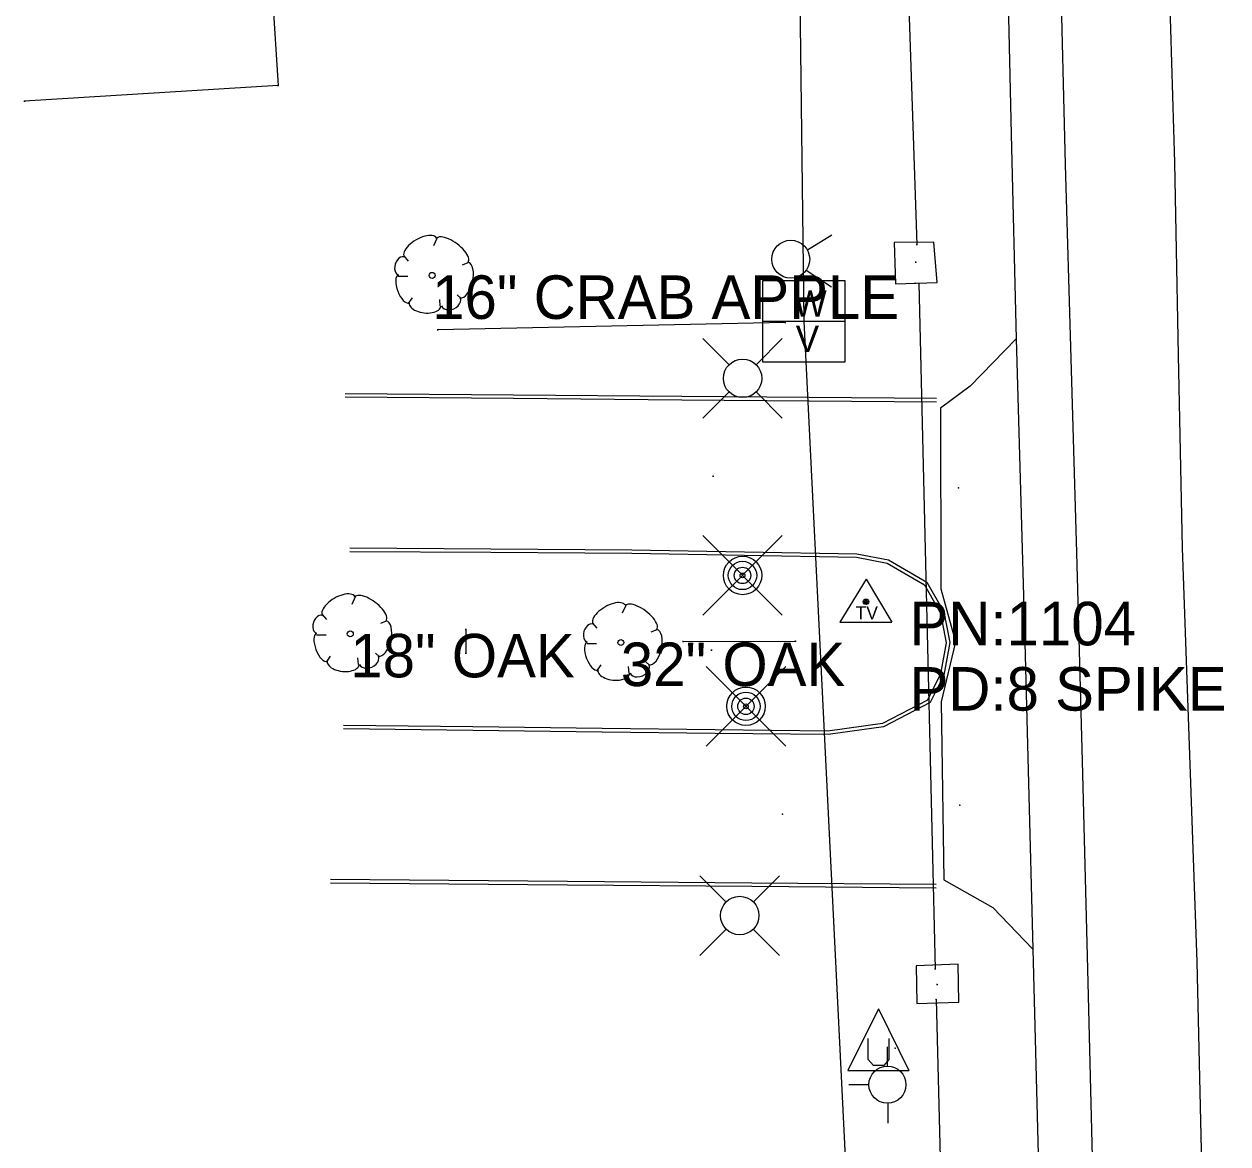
# Model space of a CAD drawing. Extents: x 1930288 to 1941089, y 588389 to 611475.
# Drawn here: x 1930751.7 to 1930890, y 597675.1 to 597803.8 of the extents above; entities that cross this region are included whole.
import ezdxf

# ---------------------------------------------------------------- set-up
doc = ezdxf.new("R2010")
doc.units = 0
for name, color, linetype in [('S_BUILDING', 7, 'Continuous'), ('S_CURB', 7, 'Continuous'), ('S_DRG_PT_SYM', 7, 'Continuous'), ('S_DRIVEWAY', 7, 'Continuous'), ('S_DROP_INLET', 7, 'Continuous'), ('S_EDGE_PAVEMENT', 7, 'Continuous'), ('S_LANDSCAPING', 7, 'Continuous'), ('S_MSC_PT_SYM', 7, 'Continuous'), ('S_PAVEMENT_CROWN', 7, 'Continuous'), ('S_SECONDARY_CTL', 7, 'Continuous'), ('S_SECONDARY_CTL_ANNOT', 7, 'Continuous'), ('S_SHOULDER', 7, 'Continuous'), ('S_SIGN', 7, 'Continuous'), ('S_STORM_SEWER', 7, 'Continuous'), ('S_STR_PT_SYM', 7, 'Continuous'), ('S_TREE', 7, 'Continuous'), ('S_TREE_ANNOT', 7, 'Continuous'), ('S_UNDERGROUND_CABLE', 7, 'Continuous'), ('S_UTILITY_POLE', 7, 'Continuous'), ('S_UTL_PT_SYM', 7, 'Continuous'), ('S_WATER_UTILITIES', 7, 'Continuous')]:
    doc.layers.add(name, color=color, linetype=linetype)

msp = doc.modelspace()

# ---------------------------------------------------------------- linework, layer by layer
at = {"layer": 'S_BUILDING'}
for p, q in [((1930779.32, 597821.17), (1930780.88, 597796.72)), ((1930780.88, 597796.72), (1930751.75, 597794.9))]:
    msp.add_line(p, q, dxfattribs=at)
at = {"layer": 'S_CURB'}
for points in [[(1930856.53, 597760.35), (1930841.9, 597760.46), (1930827.27, 597760.58), (1930807.94, 597760.74), (1930788.6, 597760.9)], [(1930856.53, 597760.75), (1930841.9, 597760.86), (1930827.27, 597760.98), (1930807.94, 597761.14), (1930788.61, 597761.3)], [(1930789.14, 597743.59), (1930805.34, 597743.49), (1930821.54, 597743.39), (1930834.46, 597743.16), (1930847.39, 597742.92), (1930851, 597742.23), (1930855.42, 597739.66), (1930857.37, 597736.24), (1930858.06, 597732.71), (1930857.37, 597728.98), (1930855.78, 597725.82), (1930850.43, 597723.02), (1930844.08, 597722.15), (1930831.1, 597722.29), (1930818.13, 597722.44), (1930803.26, 597722.62), (1930788.39, 597722.8)], [(1930789.14, 597743.19), (1930805.33, 597743.09), (1930821.53, 597742.99), (1930834.44, 597742.76), (1930847.35, 597742.52), (1930850.86, 597741.85), (1930855.13, 597739.36), (1930856.99, 597736.1), (1930857.65, 597732.7), (1930856.99, 597729.11), (1930855.48, 597726.12), (1930850.31, 597723.41), (1930844.06, 597722.55), (1930831.09, 597722.69), (1930818.13, 597722.84), (1930803.27, 597723.02), (1930788.4, 597723.2)], [(1930786.9, 597705.53), (1930800.51, 597705.41), (1930814.12, 597705.3), (1930835.31, 597705.13), (1930856.49, 597704.96)], [(1930786.9, 597705.13), (1930800.51, 597705.01), (1930814.12, 597704.9), (1930835.3, 597704.73), (1930856.49, 597704.56)]]:
    msp.add_lwpolyline(points, dxfattribs=at)
at = {"layer": 'S_DRG_PT_SYM'}
for points in [[(1930854.14, 597776.42), (1930854.14, 597776.47), (1930854.14, 597776.42), (1930854.09, 597776.42), (1930854.14, 597776.42), (1930854.14, 597776.37), (1930854.14, 597776.42), (1930854.19, 597776.42)], [(1930856.59, 597693.44), (1930856.59, 597693.49), (1930856.59, 597693.44), (1930856.54, 597693.44), (1930856.59, 597693.44), (1930856.59, 597693.39), (1930856.59, 597693.44), (1930856.64, 597693.44)]]:
    msp.add_lwpolyline(points, dxfattribs=at)
at = {"layer": 'S_DRIVEWAY'}
msp.add_lwpolyline([(1930865.66, 597767.61), (1930860.41, 597762.17), (1930856.98, 597759.65), (1930857.04, 597738.91), (1930858.7, 597732.8), (1930857.08, 597725.9), (1930857.36, 597705.47), (1930863.01, 597702.28), (1930867.6, 597697.51)], dxfattribs=at)
at = {"layer": 'S_DROP_INLET'}
for points in [[(1930851.66, 597778.68), (1930851.81, 597773.94), (1930856.61, 597774.1), (1930856.23, 597778.7)], [(1930856.23, 597778.7), (1930851.66, 597778.68)], [(1930854.19, 597695.59), (1930854.25, 597691.27), (1930859.1, 597691.39), (1930859.03, 597695.76)], [(1930859.03, 597695.76), (1930854.19, 597695.59)]]:
    msp.add_lwpolyline(points, dxfattribs=at)
at = {"layer": 'S_EDGE_PAVEMENT'}
msp.add_lwpolyline([(1930870.73, 597810.89), (1930871.29, 597787.65), (1930871.95, 597765.34), (1930872.62, 597743.02), (1930873.25, 597719.11), (1930873.88, 597695.2), (1930874.49, 597670.52), (1930875.1, 597645.85), (1930875.43, 597633.35), (1930875.77, 597620.85), (1930876.1, 597608.34), (1930876.44, 597595.84), (1930877.12, 597571.29), (1930877.79, 597546.75)], dxfattribs=at)
at = {"layer": 'S_LANDSCAPING'}
for p, q in [((1930829.67, 597735.85), (1930838.81, 597745)), ((1930838.81, 597735.85), (1930829.67, 597745)), ((1930834.24, 597740.43), (1930834.24, 597740.43)), ((1930830.06, 597720.82), (1930839.2, 597729.97)), ((1930839.2, 597720.82), (1930830.06, 597729.97)), ((1930834.63, 597725.39), (1930834.63, 597725.39))]:
    msp.add_line(p, q, dxfattribs=at)
for centre, radius in [((1930834.25, 597740.43), 2.21), ((1930834.24, 597740.43), 1.63), ((1930834.24, 597740.43), 0.943), ((1930834.24, 597740.43), 0.274), ((1930834.64, 597725.4), 2.21), ((1930834.63, 597725.39), 1.63), ((1930834.63, 597725.39), 0.943), ((1930834.63, 597725.39), 0.274)]:
    msp.add_circle(centre, radius, dxfattribs=at)
at = {"layer": 'S_MSC_PT_SYM'}
for points in [[(1930854.28, 597778.44), (1930854.28, 597778.49), (1930854.28, 597778.44), (1930854.23, 597778.44), (1930854.28, 597778.44), (1930854.28, 597778.39), (1930854.28, 597778.44), (1930854.33, 597778.44)], [(1930854.07, 597773.99), (1930854.07, 597774.04), (1930854.07, 597773.99), (1930854.02, 597773.99), (1930854.07, 597773.99), (1930854.07, 597773.94), (1930854.07, 597773.99), (1930854.12, 597773.99)], [(1930854.51, 597773.96), (1930854.51, 597774.01), (1930854.51, 597773.96), (1930854.46, 597773.96), (1930854.51, 597773.96), (1930854.51, 597773.91), (1930854.51, 597773.96), (1930854.56, 597773.96)], [(1930830.87, 597751.82), (1930830.87, 597751.87), (1930830.87, 597751.82), (1930830.82, 597751.82), (1930830.87, 597751.82), (1930830.87, 597751.77), (1930830.87, 597751.82), (1930830.92, 597751.82)], [(1930859.05, 597750.5), (1930859.05, 597750.55), (1930859.05, 597750.5), (1930859, 597750.5), (1930859.05, 597750.5), (1930859.05, 597750.45), (1930859.05, 597750.5), (1930859.1, 597750.5)], [(1930802.45, 597734.23), (1930802.45, 597734.28), (1930802.45, 597734.23), (1930802.4, 597734.23), (1930802.45, 597734.23), (1930802.45, 597734.18), (1930802.45, 597734.23), (1930802.5, 597734.23)], [(1930827.41, 597732.84), (1930827.41, 597732.89), (1930827.41, 597732.84), (1930827.36, 597732.84), (1930827.41, 597732.84), (1930827.41, 597732.79), (1930827.41, 597732.84), (1930827.46, 597732.84)], [(1930840.31, 597732.87), (1930840.31, 597732.92), (1930840.31, 597732.87), (1930840.26, 597732.87), (1930840.31, 597732.87), (1930840.31, 597732.82), (1930840.31, 597732.87), (1930840.36, 597732.87)], [(1930802.47, 597731.49), (1930802.47, 597731.54), (1930802.47, 597731.49), (1930802.42, 597731.49), (1930802.47, 597731.49), (1930802.47, 597731.44), (1930802.47, 597731.49), (1930802.53, 597731.49)], [(1930830.66, 597731.86), (1930830.66, 597731.91), (1930830.66, 597731.86), (1930830.61, 597731.86), (1930830.66, 597731.86), (1930830.66, 597731.81), (1930830.66, 597731.86), (1930830.71, 597731.86)], [(1930859.21, 597714.04), (1930859.21, 597714.09), (1930859.21, 597714.04), (1930859.16, 597714.04), (1930859.21, 597714.04), (1930859.21, 597713.99), (1930859.21, 597714.04), (1930859.26, 597714.04)], [(1930838.83, 597713), (1930838.83, 597713.05), (1930838.83, 597713), (1930838.78, 597713), (1930838.83, 597713), (1930838.83, 597712.95), (1930838.83, 597713), (1930838.88, 597713)], [(1930856.38, 597695.23), (1930856.38, 597695.28), (1930856.38, 597695.23), (1930856.33, 597695.23), (1930856.38, 597695.23), (1930856.38, 597695.18), (1930856.38, 597695.23), (1930856.43, 597695.23)], [(1930856.5, 597691.72), (1930856.5, 597691.77), (1930856.5, 597691.72), (1930856.45, 597691.72), (1930856.5, 597691.72), (1930856.5, 597691.67), (1930856.5, 597691.72), (1930856.55, 597691.72)], [(1930851.78, 597686.12), (1930851.78, 597686.17), (1930851.78, 597686.12), (1930851.73, 597686.12), (1930851.78, 597686.12), (1930851.78, 597686.07), (1930851.78, 597686.12), (1930851.83, 597686.12)]]:
    msp.add_lwpolyline(points, dxfattribs=at)
at = {"layer": 'S_PAVEMENT_CROWN'}
msp.add_lwpolyline([(1930883.18, 597810.9), (1930883.85, 597787.85), (1930884.29, 597765.72), (1930884.74, 597743.6), (1930885.58, 597719.82), (1930886.42, 597696.04), (1930886.99, 597671.07), (1930887.57, 597646.1), (1930887.95, 597633.52), (1930888.32, 597620.95), (1930888.7, 597608.37), (1930889.08, 597595.8), (1930889.54, 597571.36), (1930890, 597546.92)], dxfattribs=at)
at = {"layer": 'S_SECONDARY_CTL'}
for p, q in [((1930848.43, 597740.01), (1930845.42, 597735.05)), ((1930848.43, 597740.01), (1930851.38, 597735.05)), ((1930845.42, 597735.05), (1930851.38, 597735.05))]:
    msp.add_line(p, q, dxfattribs=at)
for radius in [0.311, 0.183, 0.103]:
    msp.add_circle((1930848.43, 597737.4), radius, dxfattribs=at)
at = {"layer": 'S_SHOULDER'}
msp.add_lwpolyline([(1930864.57, 597814.62), (1930865.11, 597791.12), (1930865.66, 597767.61), (1930866.16, 597750.17), (1930866.67, 597732.73), (1930867.13, 597715.12), (1930867.6, 597697.51), (1930868.2, 597673.9), (1930868.81, 597650.28), (1930869.2, 597636.59), (1930869.59, 597622.9), (1930869.98, 597609.21), (1930870.37, 597595.52), (1930871.07, 597571.18), (1930871.77, 597546.85)], dxfattribs=at)
at = {"layer": 'S_SIGN'}
for p, q in [((1930802.45, 597734.23), (1930802.47, 597731.49)), ((1930827.41, 597732.84), (1930840.31, 597732.87))]:
    msp.add_line(p, q, dxfattribs=at)
at = {"layer": 'S_STORM_SEWER'}
for p, q in [((1930850.87, 597878.26), (1930854.28, 597778.44)), ((1930854.51, 597773.96), (1930856.38, 597695.23)), ((1930856.5, 597691.72), (1930859.53, 597572.29))]:
    msp.add_line(p, q, dxfattribs=at)
at = {"layer": 'S_STR_PT_SYM'}
for points in [[(1930780.88, 597796.72), (1930780.88, 597796.77), (1930780.88, 597796.72), (1930780.83, 597796.72), (1930780.88, 597796.72), (1930780.88, 597796.67), (1930780.88, 597796.72), (1930780.93, 597796.72)], [(1930751.75, 597794.9), (1930751.75, 597794.95), (1930751.75, 597794.9), (1930751.7, 597794.9), (1930751.75, 597794.9), (1930751.75, 597794.85), (1930751.75, 597794.9), (1930751.8, 597794.9)]]:
    msp.add_lwpolyline(points, dxfattribs=at)
at = {"layer": 'S_TREE'}
for p, q in [((1930799.14, 597779.15), (1930798.75, 597778.29)), ((1930795.34, 597777.13), (1930795.84, 597776.55)), ((1930802.7, 597776.36), (1930802.04, 597776.09)), ((1930794.68, 597774.81), (1930795.8, 597774.81)), ((1930795.84, 597771.63), (1930796.31, 597772.33)), ((1930799.52, 597771.36), (1930799.45, 597772.13)), ((1930801.93, 597772.25), (1930801.46, 597772.68)), ((1930789.73, 597737.96), (1930789.35, 597737.11)), ((1930820.82, 597736.97), (1930820.43, 597736.11)), ((1930785.94, 597735.95), (1930786.44, 597735.37)), ((1930793.3, 597735.17), (1930792.64, 597734.9)), ((1930817.02, 597734.95), (1930817.52, 597734.37)), ((1930824.38, 597734.18), (1930823.72, 597733.9)), ((1930785.28, 597733.62), (1930786.4, 597733.62)), ((1930816.36, 597732.63), (1930817.48, 597732.63)), ((1930792.52, 597731.07), (1930792.06, 597731.49)), ((1930786.44, 597730.45), (1930786.91, 597731.14)), ((1930790.12, 597730.18), (1930790.04, 597730.95)), ((1930817.52, 597729.45), (1930817.99, 597730.15)), ((1930821.2, 597729.18), (1930821.13, 597729.95)), ((1930823.61, 597730.07), (1930823.14, 597730.49))]:
    msp.add_line(p, q, dxfattribs=at)
for centre in [(1930798.58, 597774.9), (1930789.18, 597733.72), (1930820.26, 597732.72)]:
    msp.add_circle(centre, 0.341, dxfattribs=at)
for centre, major_axis, ratio, start_param, end_param in [((1930797.24, 597778.1), (1.86, 1.08), 0.471018, 0, 3.141593), ((1930800.9, 597777.78), (-1.81, 1.36), 0.405113, 3.141593, 6.283186), ((1930795.01, 597775.99), (0.31, 1.03), 0.646762, 0, 3.141593), ((1930802.25, 597774.37), (0.46, 2.04), 0.482994, 3.141593, 6.283185), ((1930795.31, 597773.34), (-0.61, 1.6), 0.420543, 6.283185, 9.424777), ((1930797.77, 597771.56), (-1.83, 0.19), 0.529943, 0, 3.141593), ((1930800.73, 597771.85), (1.09, 0.46), 0.711534, 3.141592, 6.283185), ((1930787.84, 597736.92), (1.86, 1.08), 0.471018, 0, 3.141593), ((1930791.49, 597736.6), (-1.81, 1.36), 0.405113, 3.141593, 6.283186), ((1930818.92, 597735.92), (1.86, 1.08), 0.471018, 0, 3.141593), ((1930822.58, 597735.6), (-1.81, 1.36), 0.405113, 3.141593, 6.283186), ((1930785.61, 597734.81), (0.31, 1.03), 0.646762, 0, 3.141593), ((1930792.85, 597733.19), (0.46, 2.04), 0.482994, 3.141593, 6.283185), ((1930816.69, 597733.81), (0.31, 1.03), 0.646762, 0, 3.141593), ((1930823.93, 597732.19), (0.46, 2.04), 0.482994, 3.141593, 6.283185), ((1930785.91, 597732.16), (-0.61, 1.6), 0.420543, 6.283185, 9.424777), ((1930816.99, 597731.16), (-0.61, 1.6), 0.420543, 6.283185, 9.424777), ((1930788.37, 597730.38), (-1.83, 0.19), 0.529943, 0, 3.141593), ((1930791.33, 597730.67), (1.09, 0.46), 0.711534, 3.141592, 6.283185), ((1930822.41, 597729.67), (1.09, 0.46), 0.711534, 3.141592, 6.283185), ((1930819.45, 597729.38), (-1.83, 0.19), 0.529943, 0, 3.141593)]:
    msp.add_ellipse(centre, major_axis=major_axis, ratio=ratio, start_param=start_param, end_param=end_param, dxfattribs=at)
at = {"layer": 'S_UNDERGROUND_CABLE'}
for p, q in [((1930849.87, 597690.66), (1930846.35, 597683.57)), ((1930849.87, 597690.66), (1930853.36, 597683.57)), ((1930848.67, 597684.81), (1930848.67, 597687.25)), ((1930851.04, 597687.25), (1930851.04, 597684.81)), ((1930849.29, 597684.15), (1930848.67, 597684.81)), ((1930851.04, 597684.81), (1930850.49, 597684.15)), ((1930846.35, 597683.57), (1930853.36, 597683.57)), ((1930850.49, 597684.15), (1930849.29, 597684.15))]:
    msp.add_line(p, q, dxfattribs=at)
at = {"layer": 'S_UTILITY_POLE'}
for p, q in [((1930832.65, 597764.65), (1930829.67, 597767.63)), ((1930835.83, 597764.65), (1930838.81, 597767.63)), ((1930832.65, 597761.47), (1930829.67, 597758.49)), ((1930835.83, 597761.47), (1930838.81, 597758.49)), ((1930832.32, 597702.94), (1930829.34, 597705.92)), ((1930835.5, 597702.94), (1930838.48, 597705.92)), ((1930832.32, 597699.76), (1930829.34, 597696.78)), ((1930835.5, 597699.76), (1930838.48, 597696.78)), ((1930850.89, 597684.04), (1930850.89, 597686.29)), ((1930848.8, 597681.91), (1930846.47, 597681.91)), ((1930850.97, 597677.49), (1930850.97, 597679.82))]:
    msp.add_line(p, q, dxfattribs=at)
for centre, radius in [((1930834.25, 597763.07), 2.21), ((1930833.92, 597701.36), 2.21), ((1930850.89, 597681.93), 2.13)]:
    msp.add_circle(centre, radius, dxfattribs=at)
at = {"layer": 'S_UTL_PT_SYM'}
for points in [[(1930854.28, 597778.44), (1930854.28, 597778.49), (1930854.28, 597778.44), (1930854.23, 597778.44), (1930854.28, 597778.44), (1930854.28, 597778.39), (1930854.28, 597778.44), (1930854.33, 597778.44)], [(1930854.14, 597776.42), (1930854.14, 597776.47), (1930854.14, 597776.42), (1930854.09, 597776.42), (1930854.14, 597776.42), (1930854.14, 597776.37), (1930854.14, 597776.42), (1930854.19, 597776.42)], [(1930854.07, 597773.99), (1930854.07, 597774.04), (1930854.07, 597773.99), (1930854.02, 597773.99), (1930854.07, 597773.99), (1930854.07, 597773.94), (1930854.07, 597773.99), (1930854.12, 597773.99)], [(1930854.51, 597773.96), (1930854.51, 597774.01), (1930854.51, 597773.96), (1930854.46, 597773.96), (1930854.51, 597773.96), (1930854.51, 597773.91), (1930854.51, 597773.96), (1930854.56, 597773.96)], [(1930799.23, 597768.65), (1930799.23, 597768.7), (1930799.23, 597768.65), (1930799.18, 597768.65), (1930799.23, 597768.65), (1930799.23, 597768.6), (1930799.23, 597768.65), (1930799.28, 597768.65)], [(1930839.15, 597769.5), (1930839.15, 597769.55), (1930839.15, 597769.5), (1930839.1, 597769.5), (1930839.15, 597769.5), (1930839.15, 597769.45), (1930839.15, 597769.5), (1930839.2, 597769.5)], [(1930841.28, 597769.64), (1930841.28, 597769.69), (1930841.28, 597769.64), (1930841.23, 597769.64), (1930841.28, 597769.64), (1930841.28, 597769.59), (1930841.28, 597769.64), (1930841.33, 597769.64)], [(1930856.38, 597695.23), (1930856.38, 597695.28), (1930856.38, 597695.23), (1930856.33, 597695.23), (1930856.38, 597695.23), (1930856.38, 597695.18), (1930856.38, 597695.23), (1930856.43, 597695.23)], [(1930856.59, 597693.44), (1930856.59, 597693.49), (1930856.59, 597693.44), (1930856.54, 597693.44), (1930856.59, 597693.44), (1930856.59, 597693.39), (1930856.59, 597693.44), (1930856.64, 597693.44)], [(1930856.5, 597691.72), (1930856.5, 597691.77), (1930856.5, 597691.72), (1930856.45, 597691.72), (1930856.5, 597691.72), (1930856.5, 597691.67), (1930856.5, 597691.72), (1930856.55, 597691.72)]]:
    msp.add_lwpolyline(points, dxfattribs=at)
at = {"layer": 'S_WATER_UTILITIES'}
for p, q in [((1930839.97, 597879.92), (1930841.28, 597769.64)), ((1930841.69, 597777.82), (1930844.51, 597779.55)), ((1930841.56, 597775.51), (1930844.47, 597773.58)), ((1930836.57, 597774.33), (1930845.99, 597774.33)), ((1930836.57, 597764.92), (1930836.57, 597774.33)), ((1930845.99, 597774.33), (1930845.99, 597764.92)), ((1930839.15, 597769.5), (1930799.23, 597768.65)), ((1930836.57, 597769.64), (1930845.99, 597769.64)), ((1930841.28, 597769.64), (1930850.82, 597577.28)), ((1930845.99, 597764.92), (1930836.57, 597764.92))]:
    msp.add_line(p, q, dxfattribs=at)
msp.add_circle((1930839.78, 597776.76), 2.18, dxfattribs=at)

# ---------------------------------------------------------------- texts
at = {"layer": 'S_SECONDARY_CTL'}
msp.add_text('TV', height=1.5, rotation=360, dxfattribs=at).set_placement((1930847.23, 597735.38))
at = {"layer": 'S_SECONDARY_CTL_ANNOT'}
for s, p in [('PN:1104', (1930853.43, 597732.4)), ('PD:8 SPIKE', (1930853.43, 597724.9))]:
    msp.add_text(s, height=5, dxfattribs=at).set_placement(p)
at = {"layer": 'S_TREE_ANNOT'}
for s, p in [('16" CRAB APPLE', (1930798.58, 597769.9)), ('18" OAK', (1930789.18, 597728.72)), ('32" OAK', (1930820.26, 597727.72))]:
    msp.add_text(s, height=5, dxfattribs=at).set_placement(p)
at = {"layer": 'S_WATER_UTILITIES'}
for s, p in [('W', (1930840.12, 597770.17)), ('V', (1930840.36, 597766.11))]:
    msp.add_text(s, height=3, rotation=360, dxfattribs=at).set_placement(p)

doc.saveas('drawing.dxf')
